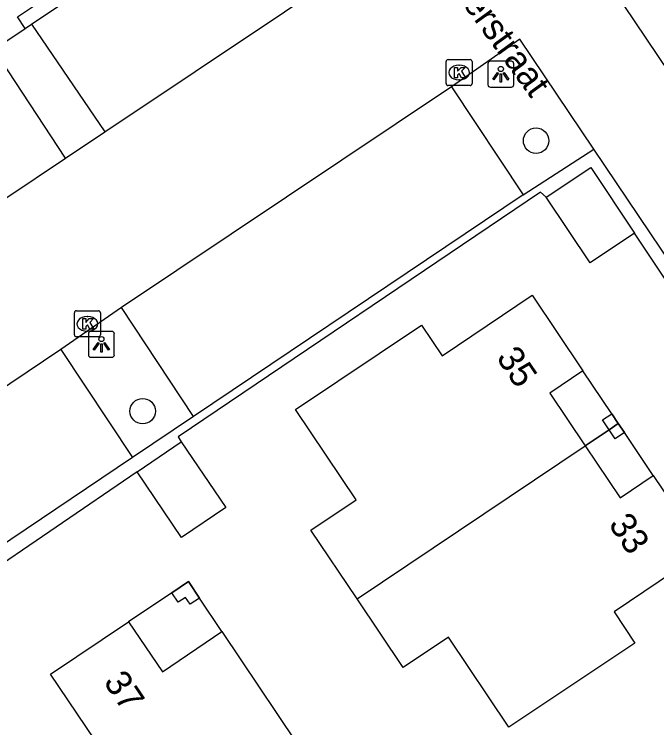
# Model space of a CAD drawing. Extents: x 158797 to 159887, y 384318 to 385255.
# Drawn here: x 158971.6 to 158996.31, y 384679.81 to 384707.27 of the extents above; entities that cross this region are included whole.
import ezdxf

# ---------------------------------------------------------------- set-up
doc = ezdxf.new("R2010")
doc.units = 0
for name, color, linetype in [('IMGEO_Boom', 7, 'Continuous'), ('IMGEO_Haag', 7, 'Continuous'), ('IMGEO_Kolk', 7, 'Continuous'), ('IMGEO_Lichtpunt', 7, 'Continuous'), ('IMGEO_Openbare_ruimte_label', 7, 'Continuous'), ('IMGEO_Pand', 7, 'Continuous'), ('IMGEO_Pand_nummerreeks', 7, 'Continuous'), ('IMGEO_Pand_overbouw', 7, 'Continuous'), ('IMGEO_Parkeervlak_open', 7, 'Continuous'), ('IMGEO_Rijbaan_lokaal_open', 7, 'Continuous'), ('IMGEO_Voetpad_open', 7, 'Continuous')]:
    doc.layers.add(name, color=color, linetype=linetype)

msp = doc.modelspace()

# ---------------------------------------------------------------- linework, layer by layer
at = {"layer": 'IMGEO_Boom'}
for centre in [(158991.667, 384702.404), (158976.538, 384691.995)]:
    msp.add_circle(centre, 0.489, dxfattribs=at)
at = {"layer": 'IMGEO_Haag'}
for points in [[(158972.017, 384706.723), (158971.722, 384707.173), (158984.222, 384715.527), (158980.257, 384721.539), (158980.664, 384721.786)], [(158991.17, 384700.32), (158993.889, 384702.078)], [(158992.052, 384700.227), (158991.832, 384700.418), (158977.899, 384691.005), (158978.017, 384690.809)], [(158998.642, 384695.007), (158998.192, 384694.724), (158995.45, 384698.84)], [(158978.488, 384691.787), (158976.14, 384690.213)], [(158976.326, 384689.664), (158970.085, 384685.407), (158969.689, 384685.861)]]:
    msp.add_lwpolyline(points, dxfattribs=at)
at = {"layer": 'IMGEO_Kolk'}
for p, q in [((158988.205, 384704.6), (158988.205, 384705.452)), ((158988.28, 384705.526), (158989.132, 384705.526)), ((158989.206, 384705.452), (158989.206, 384704.6)), ((158988.693, 384705.306), (158988.718, 384705.306)), ((158988.716, 384704.746), (158988.691, 384704.746)), ((158989.132, 384704.526), (158988.28, 384704.526)), ((158973.911, 384694.931), (158973.911, 384695.783)), ((158973.986, 384695.857), (158974.838, 384695.857)), ((158974.912, 384695.783), (158974.912, 384694.931)), ((158974.399, 384695.637), (158974.424, 384695.637)), ((158974.422, 384695.077), (158974.397, 384695.077)), ((158974.838, 384694.857), (158973.986, 384694.857))]:
    msp.add_line(p, q, dxfattribs=at)
for points in [[(158988.205, 384704.6), (158988.205, 384705.452)], [(158988.28, 384705.526), (158989.132, 384705.526)], [(158989.206, 384705.452), (158989.206, 384704.6)], [(158988.526, 384705.226), (158988.649, 384705.226), (158988.649, 384705.075), (158988.779, 384705.226), (158988.943, 384705.226), (158988.797, 384705.075), (158988.95, 384704.826), (158988.798, 384704.826), (158988.713, 384704.99), (158988.649, 384704.923), (158988.649, 384704.826), (158988.526, 384704.826), (158988.526, 384705.226)], [(158989.132, 384704.526), (158988.28, 384704.526)], [(158973.911, 384694.931), (158973.911, 384695.783)], [(158973.986, 384695.857), (158974.838, 384695.857)], [(158974.912, 384695.783), (158974.912, 384694.931)], [(158974.232, 384695.557), (158974.355, 384695.557), (158974.355, 384695.406), (158974.485, 384695.557), (158974.649, 384695.557), (158974.503, 384695.406), (158974.656, 384695.157), (158974.504, 384695.157), (158974.419, 384695.321), (158974.355, 384695.254), (158974.355, 384695.157), (158974.232, 384695.157), (158974.232, 384695.557)], [(158974.838, 384694.857), (158973.986, 384694.857)]]:
    msp.add_lwpolyline(points, dxfattribs=at)
for centre, start, end in [((158988.282, 384705.45), 91.552, 178.448), ((158988.282, 384705.45), 91.552, 178.448), ((158989.13, 384705.45), 1.552, 88.448), ((158989.13, 384705.45), 1.552, 88.448), ((158988.282, 384704.602), 181.552, 268.448), ((158988.282, 384704.602), 181.552, 268.448), ((158989.13, 384704.602), 271.552, 358.448), ((158989.13, 384704.602), 271.552, 358.448), ((158973.988, 384695.781), 91.552, 178.448), ((158973.988, 384695.781), 91.552, 178.448), ((158974.836, 384695.781), 1.552, 88.448), ((158974.836, 384695.781), 1.552, 88.448), ((158973.988, 384694.933), 181.552, 268.448), ((158973.988, 384694.933), 181.552, 268.448), ((158974.836, 384694.933), 271.552, 358.448), ((158974.836, 384694.933), 271.552, 358.448)]:
    msp.add_arc(centre, 0.0765, start, end, dxfattribs=at)
for centre, major_axis, ratio, start_param, end_param in [((158988.692, 384705.026), (-0.387, 0.002), 0.722429, 4.712389, 7.853982), ((158988.717, 384705.026), (-0.39, 0.002), 0.717154, 1.570796, 4.712389), ((158974.398, 384695.357), (-0.387, 0.002), 0.722429, 4.712389, 7.853982), ((158974.423, 384695.357), (-0.39, 0.002), 0.717154, 1.570796, 4.712389)]:
    msp.add_ellipse(centre, major_axis=major_axis, ratio=ratio, start_param=start_param, end_param=end_param, dxfattribs=at)
at = {"layer": 'IMGEO_Lichtpunt'}
for p, q in [((158990.715, 384705.462), (158989.907, 384705.462)), ((158990.715, 384705.462), (158989.907, 384705.462)), ((158989.813, 384705.367), (158989.813, 384704.56)), ((158989.813, 384705.367), (158989.813, 384704.56)), ((158990.809, 384704.56), (158990.809, 384705.367)), ((158990.809, 384704.56), (158990.809, 384705.367)), ((158989.907, 384704.466), (158990.715, 384704.466)), ((158989.907, 384704.466), (158990.715, 384704.466)), ((158974.451, 384694.972), (158974.451, 384694.165)), ((158974.451, 384694.972), (158974.451, 384694.165)), ((158975.353, 384695.067), (158974.545, 384695.067)), ((158975.353, 384695.067), (158974.545, 384695.067)), ((158975.447, 384694.165), (158975.447, 384694.972)), ((158975.447, 384694.165), (158975.447, 384694.972)), ((158974.545, 384694.071), (158975.353, 384694.071)), ((158974.545, 384694.071), (158975.353, 384694.071))]:
    msp.add_line(p, q, dxfattribs=at)
for points in [[(158990.187, 384705.031), (158990.226, 384705.003), (158990.038, 384704.741), (158990, 384704.768), (158990.187, 384705.031)], [(158990.289, 384704.983), (158990.336, 384704.983), (158990.336, 384704.661), (158990.289, 384704.661), (158990.289, 384704.983)], [(158990.399, 384705.003), (158990.437, 384705.03), (158990.624, 384704.768), (158990.585, 384704.74), (158990.399, 384705.003)], [(158974.825, 384694.636), (158974.864, 384694.608), (158974.676, 384694.346), (158974.638, 384694.373), (158974.825, 384694.636)], [(158974.927, 384694.588), (158974.974, 384694.588), (158974.974, 384694.266), (158974.927, 384694.266), (158974.927, 384694.588)], [(158975.037, 384694.608), (158975.075, 384694.635), (158975.262, 384694.373), (158975.223, 384694.345), (158975.037, 384694.608)]]:
    msp.add_lwpolyline(points, dxfattribs=at)
for centre in [(158990.312, 384705.165), (158974.95, 384694.77)]:
    msp.add_circle(centre, 0.0994, dxfattribs=at)
for centre, start, end in [((158989.907, 384705.367), 90, 180), ((158989.907, 384705.367), 90, 180), ((158990.715, 384705.367), 0, 90), ((158990.715, 384705.367), 0, 90), ((158989.907, 384704.56), 180, 270), ((158989.907, 384704.56), 180, 270), ((158990.715, 384704.56), 270, 0), ((158990.715, 384704.56), 270, 360), ((158974.545, 384694.972), 90, 180), ((158974.545, 384694.972), 90, 180), ((158975.353, 384694.972), 0, 90), ((158975.353, 384694.972), 0, 90), ((158974.545, 384694.165), 180, 270), ((158974.545, 384694.165), 180, 270), ((158975.353, 384694.165), 270, 0), ((158975.353, 384694.165), 270, 360)]:
    msp.add_arc(centre, 0.0946, start, end, dxfattribs=at)
at = {"layer": 'IMGEO_Pand'}
for points in [[(158992.052, 384700.227), (158993.771, 384701.378), (158995.45, 384698.84)], [(158995.45, 384698.84), (158993.749, 384697.7), (158992.052, 384700.227)], [(158984.781, 384684.772), (158983.004, 384687.418), (158984.745, 384688.583), (158982.41, 384692.063), (158987.254, 384695.305), (158988.06, 384694.119), (158991.51, 384696.461), (158993.462, 384693.548), (158992.194, 384692.689), (158993.552, 384690.663)], [(158994.474, 384691.282), (158994.222, 384691.658), (158994.574, 384691.895), (158994.827, 384691.519)], [(158994.827, 384691.519), (158995.061, 384691.172), (158994.708, 384690.934), (158994.474, 384691.282)], [(158994.474, 384691.282), (158994.827, 384691.519)], [(158978.017, 384690.809), (158979.73, 384688.292), (158978.026, 384687.132), (158976.326, 384689.664)], [(158976.326, 384689.664), (158978.017, 384690.809)], [(158993.552, 384690.663), (158994.895, 384688.659), (158996.173, 384689.52), (158998.134, 384686.609), (158994.667, 384684.273), (158995.465, 384683.072), (158990.615, 384679.83), (158988.303, 384683.292), (158986.558, 384682.126), (158984.781, 384684.772)], [(158984.781, 384684.772), (158993.552, 384690.663)], [(158978.36, 384684.562), (158978.18, 384684.83), (158977.897, 384684.644), (158977.663, 384685.005), (158978.294, 384685.433), (158978.718, 384684.801), (158978.36, 384684.562)], [(158975.391, 384678.315), (158972.994, 384681.876), (158975.99, 384683.884), (158977.304, 384681.96), (158979.58, 384683.515), (158983.867, 384677.125)]]:
    msp.add_lwpolyline(points, dxfattribs=at)
at = {"layer": 'IMGEO_Pand_overbouw'}
for points in [[(158993.552, 384690.663), (158994.474, 384691.282), (158994.827, 384691.519), (158994.574, 384691.895), (158993.462, 384693.548), (158992.194, 384692.689)], [(158995.061, 384691.172), (158994.827, 384691.519), (158994.474, 384691.282), (158993.552, 384690.663), (158994.895, 384688.659), (158996.173, 384689.52)], [(158975.99, 384683.884), (158977.304, 384681.96), (158979.58, 384683.515), (158978.718, 384684.801), (158978.294, 384685.433), (158977.663, 384685.005)]]:
    msp.add_lwpolyline(points, close=True, dxfattribs=at)
at = {"layer": 'IMGEO_Parkeervlak_open'}
for points in [[(158972.264, 384706.889), (158982.666, 384713.882)], [(158988.412, 384704.475), (158991.17, 384700.32)], [(158991.17, 384700.32), (158978.488, 384691.787)], [(158978.488, 384691.787), (158975.726, 384695.98)], [(158973.391, 384694.368), (158976.14, 384690.213)], [(158976.14, 384690.213), (158969.689, 384685.861)]]:
    msp.add_lwpolyline(points, dxfattribs=at)
at = {"layer": 'IMGEO_Rijbaan_lokaal_open'}
for points in [[(159017.243, 384755.079), (159004.006, 384746.223), (158979.975, 384730.054), (158992.379, 384711.59), (159004.736, 384693.195)], [(158975.08, 384702.746), (158985.469, 384709.698)], [(158993.889, 384702.078), (158991.044, 384706.311), (158988.412, 384704.475)], [(158988.412, 384704.475), (158975.726, 384695.98)], [(158973.571, 384701.736), (158975.08, 384702.746)], [(158998.642, 384695.007), (158993.889, 384702.078)], [(158971.272, 384700.198), (158973.571, 384701.736)], [(158975.726, 384695.98), (158973.391, 384694.368)], [(158973.391, 384694.368), (158966.82, 384689.961)]]:
    msp.add_lwpolyline(points, dxfattribs=at)
at = {"layer": 'IMGEO_Voetpad_open'}
for points in [[(158972.017, 384706.723), (158972.264, 384706.889)], [(158972.264, 384706.889), (158975.08, 384702.746)], [(158971.076, 384706.091), (158972.017, 384706.723)], [(158973.571, 384701.736), (158970.818, 384705.917)]]:
    msp.add_lwpolyline(points, dxfattribs=at)

# ---------------------------------------------------------------- texts
at = {"layer": 'IMGEO_Openbare_ruimte_label'}
msp.add_text('Schaduwmaskerstraat', height=1, rotation=306.0105, dxfattribs=at).set_placement((158983.701, 384714.716))
at = {"layer": 'IMGEO_Pand_nummerreeks'}
for s, rotation, p in [('35', 303.8272, (158990.113, 384694.055)), ('33', 303.9647, (158994.427, 384687.637)), ('37', 303.9475, (158975.007, 384681.572))]:
    msp.add_text(s, height=1, rotation=rotation, dxfattribs=at).set_placement(p)

doc.saveas('drawing.dxf')
